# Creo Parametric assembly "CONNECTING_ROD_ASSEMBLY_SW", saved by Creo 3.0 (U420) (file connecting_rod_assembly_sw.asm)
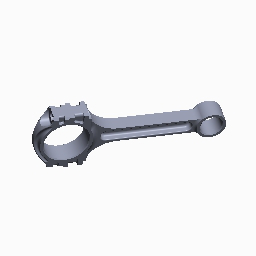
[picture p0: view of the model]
Units: millimeter Kilogram Sec (mmKs); MM, KILOGRAM, SECS

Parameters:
  CAD_SYSTEM = "SOLIDWORKS_ASM"
  DEX_MASTER = "connecting_rod_assembly_sw"
  MODEL_VERSION = "0"
  MODEL_DATE = "12/13/2013 06:16:44"
  TIM_STATUS = "Missing Ref Model"
  REF_LINK = "D:\009_demo_dev\001_Creo_Trail\engine_shaft_asm_v5\connecting_rod_assembly_sw.SL"
  NATIVE_NAME = "connecting_rod_assembly_sw"

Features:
  1. coordinate system "CONNECTING_ROD_ASSEMBLY_SW"
  2. component "CONNECTING_ROD_1_SW"
  3. component "CONNECTING_ROD_2_SW"

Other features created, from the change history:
  imported feature "Neutral id 4"
  component interface "INTFC001"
